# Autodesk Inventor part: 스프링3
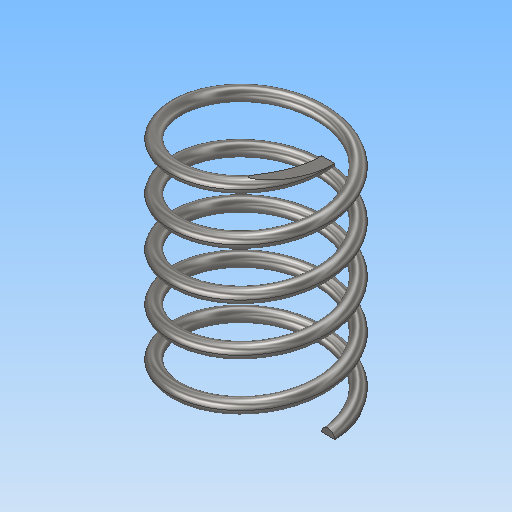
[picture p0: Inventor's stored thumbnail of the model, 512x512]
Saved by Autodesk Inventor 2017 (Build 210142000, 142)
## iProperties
Part Number: 스프링3
Material: 강철, 연강
Document SubType Name: Modeling
Designer: MRC
Density: 7.85 g/cm^3
Appearance: 반연마
Mass: 8.42324 g
Surface Area: 21.7217 cm^2
Volume: 1.07302 cm^3
Author: MRC
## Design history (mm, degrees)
sketch "스케치1"
  geometry: L1 (0, 0)-(0, 36.411); L2 (0, 36.411)-(11, 36.411); L3 (0, 0)-(11, 0); C1 r 1 at (11, 0)
  constraints: 6 end point, 2 horizontal, 1 centre point, 1 coincident, 1 vertical
  dimensions: "d0" = 36.4112 distance of L1.start L1.end (derived); "d2" = 22 diameter of L3.end L1; "d3" = 2 diameter of C1; "d4" = 22 diameter of L2.end L1
feature "코일1" pitch "d5" = 10; turns "d7" = 5; dims "d6" = 36.4112 (= d0), "d8" = 0, angle "d9" = 90 deg, angle "d10" = 90 deg, "d11" = 0, "d12" = 0
sketch "스케치2"
  geometry: L1 (-13.313, 0)-(15.035, 0); L2 (15.035, 0)-(15.035, 36.411); L3 (15.035, 36.411)-(-13.313, 36.411); L4 (-13.313, 36.411)-(-13.313, 0); 1 further point
  constraints: 8 end point, 2 parallel, 1 horizontal, 1 perpendicular
  dimensions: "d13" = 36.4112 distance of L1.end L2.end (= d0)
extrude "돌출1" sketch "스케치2" stored distance "d14" = 0; taper "d15" = 0 deg
node "솔리드1"
